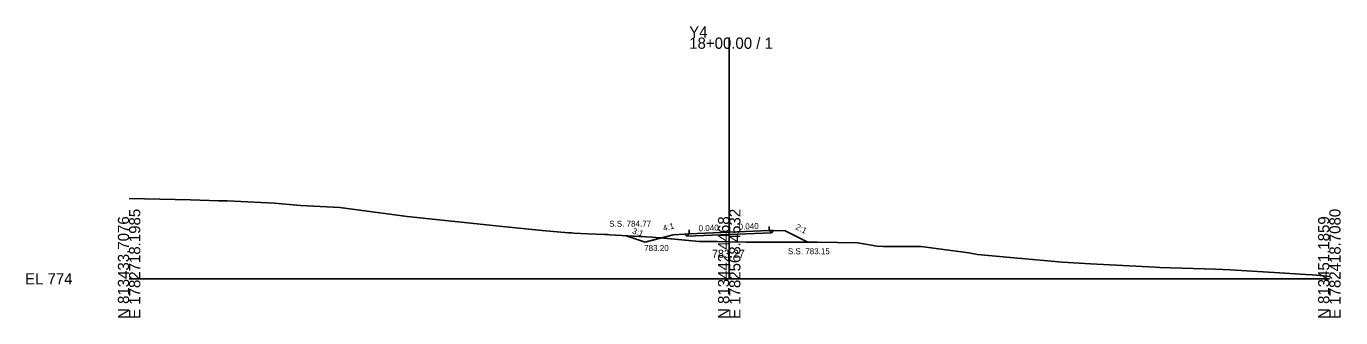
# Model space of a CAD drawing. Extents: x -26 to 3903, y -10 to 9562.
# Drawn here: x 974.3 to 1302.8, y -9.7 to 63 of the extents above; entities that cross this region are included whole.
import ezdxf

# ---------------------------------------------------------------- set-up
doc = ezdxf.new("R2010")
doc.units = 0
for name, color, linetype in [('Exist Cross Section Cell', 7, 'Continuous'), ('Exist XS Center Line Elevation Label', 7, 'Continuous'), ('Exist XS Ground Line', 7, 'Continuous'), ('Prop XS Ditch Slope Text', 7, 'Continuous'), ('Prop XS Ditch Standard Text', 7, 'Continuous'), ('Prop XS Dump Level', 7, 'Continuous'), ('Prop XS Earthwork Shape', 7, 'Continuous'), ('Prop XS EOT Tick Mark', 7, 'Continuous'), ('Prop XS Finish Grade', 7, 'Continuous'), ('Prop XS Finish Grade Earthwork', 7, 'Continuous'), ('Prop XS Finish Grade Pavement', 7, 'Continuous'), ('Prop XS Pvmt Edge Slope', 7, 'Continuous'), ('Prop XS SE Text', 7, 'Continuous'), ('Prop XS Side Slope Text', 7, 'Continuous'), ('Prop XS SS Elevation Text', 7, 'Continuous'), ('Prop XS Subgrade Earthwork', 7, 'Continuous')]:
    doc.layers.add(name, color=color, linetype=linetype)

msp = doc.modelspace()

# ---------------------------------------------------------------- linework, layer by layer
at = {"layer": 'Exist Cross Section Cell'}
for p, q in [((1150, 0), (1150, 60.24)), ((1000, 0), (1150, 0)), ((1150, 0), (1300, 0))]:
    msp.add_line(p, q, dxfattribs=at)
at = {"layer": 'Exist XS Ground Line'}
for p, q in [((1000, 20.08), (1003.83, 19.96)), ((1003.83, 19.96), (1015.33, 19.7)), ((1015.33, 19.7), (1022.38, 19.5)), ((1022.38, 19.5), (1024.49, 19.46)), ((1024.49, 19.46), (1036.31, 18.93)), ((1036.31, 18.93), (1042.88, 18.34)), ((1042.88, 18.34), (1052.7, 17.8)), ((1052.7, 17.8), (1069.52, 15.59)), ((1069.52, 15.59), (1093.32, 13.08)), ((1093.32, 13.08), (1103.26, 12.04)), ((1103.26, 12.04), (1109.84, 11.51)), ((1109.84, 11.51), (1110.61, 11.47)), ((1110.61, 11.47), (1111.19, 11.4)), ((1111.19, 11.4), (1114.59, 11.26)), ((1114.59, 11.26), (1118.88, 11.11)), ((1118.88, 11.11), (1119.57, 11.05)), ((1119.57, 11.05), (1120.2, 11.02)), ((1120.2, 11.02), (1130.71, 10.38)), ((1130.71, 10.38), (1132.75, 10.23)), ((1132.75, 10.23), (1142.52, 9.33)), ((1142.52, 9.33), (1147.04, 9.32)), ((1147.04, 9.32), (1150, 9.27)), ((1150, 9.27), (1154.2, 9.19)), ((1154.2, 9.19), (1172.04, 9.14)), ((1172.04, 9.14), (1182.06, 9.02)), ((1182.06, 9.02), (1186.98, 8.15)), ((1186.98, 8.15), (1188.47, 8.04)), ((1188.47, 8.04), (1197.86, 8.06)), ((1197.86, 8.06), (1198.59, 8.01)), ((1198.59, 8.01), (1209.88, 6.48)), ((1209.88, 6.48), (1210.7, 6.34)), ((1210.7, 6.34), (1212.02, 6.12)), ((1212.02, 6.12), (1233.19, 4.19)), ((1233.19, 4.19), (1240.3, 3.74)), ((1240.3, 3.74), (1256.49, 2.93)), ((1256.49, 2.93), (1257.65, 2.87)), ((1257.65, 2.87), (1271.55, 2.42)), ((1271.55, 2.42), (1275.19, 2.26)), ((1275.19, 2.26), (1287.51, 1.52)), ((1287.51, 1.52), (1294.04, 1.09)), ((1294.04, 1.09), (1295.67, 1.01)), ((1295.67, 1.01), (1296.82, 0.91)), ((1296.82, 0.91), (1297.62, 0.81)), ((1297.62, 0.81), (1300, 0.56))]:
    msp.add_line(p, q, dxfattribs=at)
at = {"layer": 'Prop XS Dump Level'}
for p, q in [((1140, 11.27), (1150, 11.67)), ((1150, 11.67), (1160, 12.07))]:
    msp.add_line(p, q, dxfattribs=at)
at = {"layer": 'Prop XS Earthwork Shape'}
for points in [[(1124.28, 10.77), (1130.71, 10.38), (1132.75, 10.23), (1133.03, 10.21), (1129, 9.2)], [(1133.03, 10.21), (1142.52, 9.33), (1147.04, 9.32), (1150, 9.27), (1154.2, 9.19), (1169.68, 9.15), (1164, 11.99), (1161.1, 12.05), (1160.56, 11.51), (1150.02, 11.09), (1139.39, 10.66), (1138.87, 11.18), (1136, 10.95)]]:
    msp.add_lwpolyline(points, close=True, dxfattribs=at)
at = {"layer": 'Prop XS EOT Tick Mark'}
for p, q in [((1140, 11.27), (1140, 12.27)), ((1160, 12.07), (1160, 13.07))]:
    msp.add_line(p, q, dxfattribs=at)
at = {"layer": 'Prop XS Finish Grade'}
for p, q in [((1140, 11.27), (1138.87, 11.18)), ((1160, 12.07), (1161.1, 12.05))]:
    msp.add_line(p, q, dxfattribs=at)
at = {"layer": 'Prop XS Finish Grade Earthwork'}
for p, q in [((1129, 9.2), (1124.28, 10.77)), ((1136, 10.95), (1129, 9.2)), ((1138.87, 11.18), (1136, 10.95)), ((1161.1, 12.05), (1164, 11.99)), ((1164, 11.99), (1169.68, 9.15))]:
    msp.add_line(p, q, dxfattribs=at)
at = {"layer": 'Prop XS Finish Grade Pavement'}
for p, q in [((1140, 11.27), (1150, 11.67)), ((1150, 11.67), (1160, 12.07))]:
    msp.add_line(p, q, dxfattribs=at)
at = {"layer": 'Prop XS Pvmt Edge Slope'}
for p, q in [((1140, 11.27), (1139.39, 10.66)), ((1160, 12.07), (1160.56, 11.51))]:
    msp.add_line(p, q, dxfattribs=at)
at = {"layer": 'Prop XS Subgrade Earthwork'}
for p, q in [((1139.39, 10.66), (1138.87, 11.18)), ((1139.39, 10.66), (1150.02, 11.09)), ((1150.02, 11.09), (1160.56, 11.51)), ((1160.56, 11.51), (1161.1, 12.05))]:
    msp.add_line(p, q, dxfattribs=at)

# ---------------------------------------------------------------- texts
at = {"layer": 'Exist Cross Section Cell'}
for s, p in [('Y4', (1140, 60.24)), ('18+00.00 / 1', (1140, 57.44)), ('EL 774', (974, -1.4))]:
    msp.add_text(s, height=2.8, dxfattribs=at).set_placement(p)
for s, p in [('E 1782718.1985', (1002.8, -10)), ('E 1782568.4532', (1152.8, -10)), ('E 1782418.7080', (1302.8, -10)), ('N 813433.7076', (1000, -10)), ('N 813442.4468', (1150, -10)), ('N 813451.1859', (1300, -10))]:
    msp.add_text(s, height=2.8, rotation=90, dxfattribs=at).set_placement(p)
at = {"layer": 'Exist XS Center Line Elevation Label'}
msp.add_text('783.27', height=2, dxfattribs=at).set_placement((1145.7, 5.27))
at = {"layer": 'Prop XS Ditch Slope Text'}
msp.add_text('4:1', height=1.5, rotation=14.0362, dxfattribs=at).set_placement((1133.64, 11.9))
at = {"layer": 'Prop XS Ditch Standard Text'}
msp.add_text('783.20', height=1.5, dxfattribs=at).set_placement((1128.74, 6.95))
at = {"layer": 'Prop XS Dump Level'}
for p in [(1136, 10.91), (1164, 11.95)]:
    msp.add_text('Case1', height=0.04, dxfattribs=at).set_placement(p)
at = {"layer": 'Prop XS SE Text'}
for p in [(1142.38, 11.86), (1152.38, 12.26)]:
    msp.add_text('0.040', height=1.5, rotation=2.2906, dxfattribs=at).set_placement(p)
at = {"layer": 'Prop XS Side Slope Text'}
for s, rotation, p in [('2:1', 333.4349, (1166.43, 12.45)), ('3:1', 342.2871, (1125.63, 11.36))]:
    msp.add_text(s, height=1.5, rotation=rotation, dxfattribs=at).set_placement(p)
at = {"layer": 'Prop XS SS Elevation Text'}
for s, p in [('S.S. 784.77', (1120.01, 13.01)), ('S.S. 783.15', (1164.66, 6.15))]:
    msp.add_text(s, height=1.5, dxfattribs=at).set_placement(p)

doc.saveas('drawing.dxf')
